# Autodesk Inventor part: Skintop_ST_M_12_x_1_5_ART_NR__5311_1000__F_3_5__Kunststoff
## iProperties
Created: 2005-01
Part Number: Skintop_ST_M_12_x_1_5_ART_NR__5311_1000__F_3_5__Kunststoff
Material: kunststoff
Description: ST-M - Kabelverschraubung Kunststoff
Vendor: LAPP
Document SubType Name: Modeling
Designer: DB
Manufacturer: Standard
Standards Organization: Custom
CNS_NB: Skintop ST-M 12 x 1.5-ART.NR. 5311 1000-(F=3.5)
CNS_NN: ST-M
CNS_NT: Kabelverschraubung Kunststoff
CNS_NBSYN: Skintop ST-$GEW.-ART.NR. $ATN.-(F=$F.)
CNS_LINA: Skintop ST-M 12 x 1.5-ART.NR. 5311 1000-(F=3.5)
CNS_ATN: 5311 1000
CNS_GEW: M 12 x 1.5
CNS_FMIN: 3.5
CNS_FMAX: 7.0
CNS_F: 3.5
CNS_NDM: 12.0
CNS_P: 1.5
CNS_SW: 15
CNS_X: 3.800
CNS_A: 16.6
CNS_C: 30.0
CNS_D: 8.0
CNS_E: 13.0
CNS_H: 8.9
CNS_J: 3.3
CNS_K: 5.2
CNS_L: 13.2
CNS_RAL7001: X
CNS_XMAX: 3.800
CNS_MATERIAL: Kunststoff
CNS_KT: DUMMY
CNS_DENSITY: 0.000000
CNS_DENSITYUNITBASE: 0.000000
CNS_LINA2: Skintop ST-M 12 x 1.5-ART.NR. 5311 1000-(F=3.5)
PSOL_IDENT_0: {I:\Cadenas Partsolutions\data\23d-libs\lapp_kabel\skintop_metrisch\st_m.prj},162 {VTYP=3D},{NB=Skin
PSOL_IDENT_1: top ST-M 12 x 1.5-ART.NR. 5311 1000-(F=3.5)},{NN=ST-M},{DATE=2.4.2003},{GEOMDATE=22.11.2002},{VERSIO
PSOL_IDENT_2: N=v1},{LINEID=10},{LINESUBID=-1},{WBVAR=F}  {NB=Skintop ST-M 12 x 1.5-ART.NR. 5311 1000-(F=3.5)},{LI
PSOL_IDENT_3: NA=Skintop ST-M 12 x 1.5-ART.NR. 5311 1000-(F=3.5)},{KT=DUMMY},{IDNR=},{ATN=5311 1000},{GEW=M 12 x 1
PSOL_IDENT_4: .5},{FMIN=3.5},{FMAX=7.0},{F=3.5},{NDM=12.0},{P=1.5},{SW=15},{X=3.8},{A=16.6},{C=30.0},{D=8.0},{E=13
PSOL_IDENT_5: .0},{H=8.9},{J=3.3},{K=5.2},{L=13.2},{RAL7001=X},{RAL7035=},{RAL9005=},{XMAX=3.8},{MATERIAL=Kunststo
PSOL_IDENT_6: ff}
Title: Skintop ST-M 12 x 1.5-ART.NR. 5311 1000-(F=3.5)
Author: DB
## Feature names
1. Drehung1 [Revolution]
2. Extrusion1
3. Extrusion2
4. Extrusion3
5. Extrusion4
6. Extrusion5
7. Extrusion6
